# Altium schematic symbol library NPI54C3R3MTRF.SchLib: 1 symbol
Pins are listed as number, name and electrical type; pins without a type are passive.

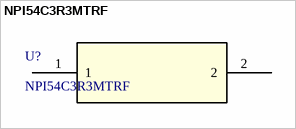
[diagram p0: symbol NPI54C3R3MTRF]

## NPI54C3R3MTRF
designator U?
No Description Available; Mfr_Name: NIC Components Corp.
footprint NPI54C3R3MTRF_NIC
pins: 1, 2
